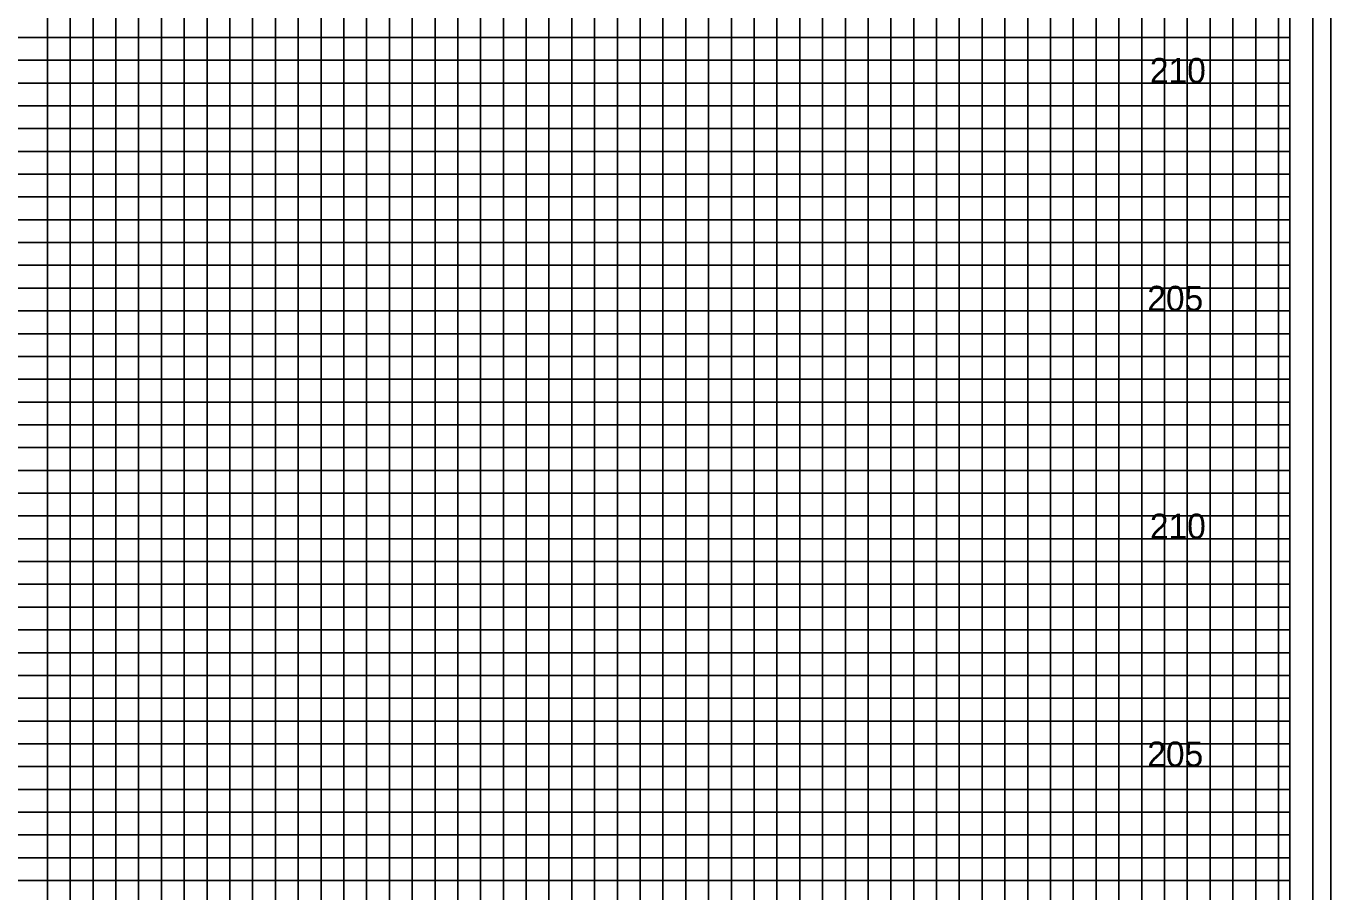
# Model space of a CAD drawing. Extents: x -4 to 103, y -2 to 209.
# Drawn here: x 74.78 to 103.4, y 103.08 to 122.08 of the extents above; entities that cross this region are included whole.
import ezdxf

# ---------------------------------------------------------------- set-up
doc = ezdxf.new("R2010")
doc.units = 0
for name, color, linetype in [('Old_Level_10', 7, 'Continuous'), ('Old_Level_17', 7, 'Continuous'), ('Old_Level_5', 7, 'Continuous'), ('Old_Level_6', 7, 'Continuous'), ('Old_Level_8', 7, 'Continuous'), ('Prop Dimension', 7, 'Continuous'), ('Typical Curb CELL', 7, 'Continuous')]:
    doc.layers.add(name, color=color, linetype=linetype)

msp = doc.modelspace()

# ---------------------------------------------------------------- linework, layer by layer
at = {"layer": 'Old_Level_10'}
for p, q in [((91.25, 70.825), (91.25, 134.25)), ((93.75, 70.825), (93.75, 134.25)), ((96.25, 70.825), (96.25, 134.25)), ((98.75, 70.825), (98.75, 134.25)), ((101.25, 70.825), (101.25, 134.25)), ((76.25, 70.825), (76.25, 132.825)), ((78.75, 70.825), (78.75, 132.825)), ((81.25, 70.825), (81.25, 132.825)), ((83.75, 70.825), (83.75, 132.825)), ((86.25, 70.825), (86.25, 132.825)), ((88.75, 70.825), (88.75, 132.825)), ((0, 120.825), (102.5, 120.825)), ((0, 118.325), (102.5, 118.325)), ((0, 115.825), (102.5, 115.825)), ((0, 113.325), (102.5, 113.325)), ((0, 110.825), (102.5, 110.825)), ((0, 108.325), (102.5, 108.325)), ((0, 105.825), (102.5, 105.825)), ((0, 103.325), (102.5, 103.325))]:
    msp.add_line(p, q, dxfattribs=at)
at = {"layer": 'Old_Level_17'}
for points in [[(90.25, 70.825), (90.25, 134.25), (90.75, 134.25), (90.75, 70.825)], [(91.75, 70.825), (91.75, 134.25), (92.25, 134.25), (92.25, 70.825)], [(92.75, 70.825), (92.75, 134.25), (93.25, 134.25), (93.25, 70.825)], [(94.25, 70.825), (94.25, 134.25), (94.75, 134.25), (94.75, 70.825)], [(95.25, 70.825), (95.25, 134.25), (95.75, 134.25), (95.75, 70.825)], [(96.75, 70.825), (96.75, 134.25), (97.25, 134.25), (97.25, 70.825)], [(97.75, 70.825), (97.75, 134.25), (98.25, 134.25), (98.25, 70.825)], [(99.25, 70.825), (99.25, 134.25), (99.75, 134.25), (99.75, 70.825)], [(100.25, 70.825), (100.25, 134.25)], [(100.25, 134.25), (100.75, 134.25), (100.75, 70.825), (101.75, 70.825), (101.75, 134.25), (102.25, 134.25), (102.25, 70.825)], [(75.25, 70.825), (75.25, 132.825), (75.75, 132.825), (75.75, 70.825)], [(76.75, 70.825), (76.75, 132.825), (77.25, 132.825), (77.25, 70.825)], [(77.75, 70.825), (77.75, 132.825), (78.25, 132.825), (78.25, 70.825)], [(79.25, 70.825), (79.25, 132.825), (79.75, 132.825), (79.75, 70.825)], [(80.25, 70.825), (80.25, 132.825), (80.75, 132.825), (80.75, 70.825)], [(81.75, 70.825), (81.75, 132.825), (82.25, 132.825), (82.25, 70.825)], [(82.75, 70.825), (82.75, 132.825), (83.25, 132.825), (83.25, 70.825)], [(84.25, 70.825), (84.25, 132.825), (84.75, 132.825), (84.75, 70.825)], [(85.25, 70.825), (85.25, 132.825), (85.75, 132.825), (85.75, 70.825)], [(86.75, 70.825), (86.75, 132.825), (87.25, 132.825), (87.25, 70.825)], [(87.75, 70.825), (87.75, 132.825), (88.25, 132.825), (88.25, 70.825)], [(89.25, 70.825), (89.25, 132.825), (89.75, 132.825), (89.75, 70.825)], [(0, 121.325), (102.5, 121.325), (102.5, 121.825), (0, 121.825)], [(0, 119.825), (102.5, 119.825), (102.5, 120.325), (0, 120.325)], [(0, 118.825), (102.5, 118.825), (102.5, 119.325), (0, 119.325)], [(0, 117.325), (102.5, 117.325), (102.5, 117.825), (0, 117.825)], [(0, 116.325), (102.5, 116.325), (102.5, 116.825), (0, 116.825)], [(0, 114.825), (102.5, 114.825), (102.5, 115.325), (0, 115.325)], [(0, 113.825), (102.5, 113.825), (102.5, 114.325), (0, 114.325)], [(0, 112.325), (102.5, 112.325), (102.5, 112.825), (0, 112.825)], [(0, 111.325), (102.5, 111.325), (102.5, 111.825), (0, 111.825)], [(0, 109.825), (102.5, 109.825), (102.5, 110.325), (0, 110.325)], [(0, 108.825), (102.5, 108.825), (102.5, 109.325), (0, 109.325)], [(0, 107.325), (102.5, 107.325), (102.5, 107.825), (0, 107.825)], [(0, 106.325), (102.5, 106.325), (102.5, 106.825), (0, 106.825)], [(0, 104.825), (102.5, 104.825), (102.5, 105.325), (0, 105.325)], [(0, 103.825), (102.5, 103.825), (102.5, 104.325), (0, 104.325)]]:
    msp.add_lwpolyline(points, dxfattribs=at)
at = {"layer": 'Old_Level_5'}
msp.add_lwpolyline([(103.4, 138.225), (-3.5, 138.225), (-3.5, 68.4), (103.4, 68.4)], close=True, dxfattribs=at)
at = {"layer": 'Old_Level_6'}
msp.add_lwpolyline([(102.5, 135.825), (0, 135.825), (0, 70.825), (102.5, 70.825)], close=True, dxfattribs=at)
at = {"layer": 'Old_Level_8'}
for points in [[(91.25, 70.825), (91.25, 134.25), (93.75, 134.25), (93.75, 70.825)], [(96.25, 70.825), (96.25, 134.25), (98.75, 134.25), (98.75, 70.825)], [(101.25, 70.825), (101.25, 134.25)], [(76.25, 70.825), (76.25, 132.825), (78.75, 132.825), (78.75, 70.825)], [(81.25, 70.825), (81.25, 132.825), (83.75, 132.825), (83.75, 70.825)], [(86.25, 70.825), (86.25, 132.825), (88.75, 132.825), (88.75, 70.825)], [(0, 118.325), (102.5, 118.325), (102.5, 120.825), (0, 120.825)], [(0, 113.325), (102.5, 113.325), (102.5, 115.825), (0, 115.825)], [(0, 108.325), (102.5, 108.325), (102.5, 110.825), (0, 110.825)], [(0, 103.325), (102.5, 103.325), (102.5, 105.825), (0, 105.825)]]:
    msp.add_lwpolyline(points, dxfattribs=at)
at = {"layer": 'Typical Curb CELL'}
msp.add_lwpolyline([(103, 136.825), (-2.8, 136.825), (-2.8, 69.825), (103, 69.825)], close=True, dxfattribs=at)

# ---------------------------------------------------------------- texts
at = {"layer": 'Prop Dimension'}
for s, p in [('210', (99.4296, 120.825)), ('205', (99.3724, 115.825)), ('210', (99.4296, 110.825)), ('205', (99.3724, 105.825))]:
    msp.add_text(s, height=0.55, dxfattribs=at).set_placement(p)

doc.saveas('drawing.dxf')
